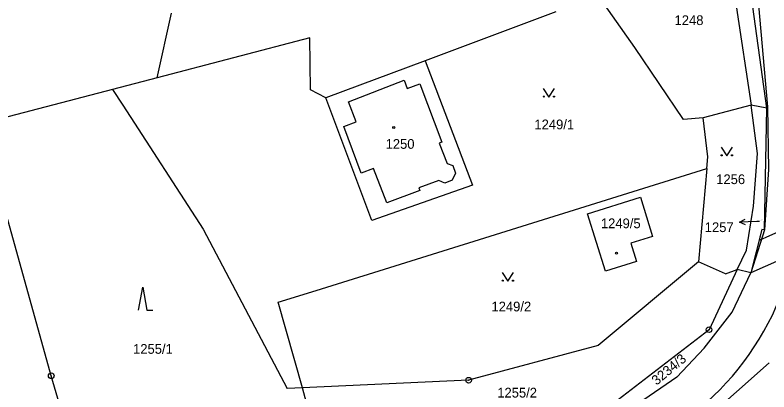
# Model space of a CAD drawing. Extents: x -736345 to -729997, y -1130177 to -1122501.
# Drawn here: x -734075.9 to -733944, y -1126906.1 to -1126840.2 of the extents above; entities that cross this region are included whole.
import ezdxf

# ---------------------------------------------------------------- set-up
doc = ezdxf.new("R2010")
doc.units = 0
for name, color, linetype in [('Vrstva 1', 7, 'Continuous'), ('Vrstva 16', 7, 'Continuous'), ('Vrstva 18', 7, 'Continuous'), ('Vrstva 19', 7, 'Continuous'), ('Vrstva 25', 7, 'Continuous'), ('Vrstva 4', 7, 'Continuous')]:
    doc.layers.add(name, color=color, linetype=linetype)

msp = doc.modelspace()

# ---------------------------------------------------------------- linework, layer by layer
at = {"layer": 'Vrstva 1'}
for points in [[(-733952.31, -1126821.15), (-733947.1, -1126855.94)], [(-733967.46, -1126845.87), (-733975.24, -1126834.74)], [(-733944.32, -1126856.48), (-733947.34, -1126834.89)], [(-733945.98, -1126836.41), (-733944.21, -1126856.25)], [(-734051.04, -1126851.13), (-734048.52, -1126839.86)], [(-733981.26, -1126839.64), (-734004.15, -1126848.16)], [(-734024.3, -1126844.16), (-734051.04, -1126851.13)], [(-734024.21, -1126853.27), (-734024.3, -1126844.16)], [(-733958.93, -1126858.46), (-733967.46, -1126845.87)], [(-734004.15, -1126848.16), (-734021.53, -1126854.63)], [(-734004.15, -1126848.16), (-733995.85, -1126869.92)], [(-734051.04, -1126851.13), (-734058.86, -1126853.17)], [(-734058.86, -1126853.17), (-734079.66, -1126858.6)], [(-734058.86, -1126853.17), (-734057.08, -1126855.91)], [(-734021.53, -1126854.63), (-734024.21, -1126853.27)], [(-734013.46, -1126876.12), (-734021.53, -1126854.63)], [(-734057.08, -1126855.91), (-734042.99, -1126877.6)], [(-733947.1, -1126855.94), (-733955.48, -1126858.17)], [(-733945.95, -1126864.4), (-733947.1, -1126855.94)], [(-733944.32, -1126856.48), (-733947.1, -1126855.94)], [(-733944.76, -1126877.73), (-733944.32, -1126856.48)], [(-733944.21, -1126856.25), (-733944.02, -1126867.2)], [(-733955.48, -1126858.17), (-733958.93, -1126858.46)], [(-733954.64, -1126864.97), (-733955.48, -1126858.17)], [(-733946.67, -1126873.57), (-733945.95, -1126864.4)], [(-734069.58, -1126903.24), (-734080.34, -1126864.84)], [(-733954.82, -1126866.98), (-733954.64, -1126864.97)], [(-734023.23, -1126888.3), (-733954.82, -1126866.98)], [(-733954.82, -1126866.98), (-733956.29, -1126883.31)], [(-733944.02, -1126867.2), (-733944.76, -1126877.73)], [(-733995.85, -1126869.92), (-734013.46, -1126876.12)], [(-733975.72, -1126874.9), (-733966.46, -1126872)], [(-733966.46, -1126872), (-733964.36, -1126878.88)], [(-733947.92, -1126881.25), (-733946.67, -1126873.57)], [(-733972.6, -1126884.94), (-733975.72, -1126874.9)], [(-734042.99, -1126877.6), (-734028.32, -1126905.45)], [(-733945.23, -1126877.65), (-733947.14, -1126885.22)], [(-733944.76, -1126877.73), (-733947.14, -1126885.22)], [(-733944.76, -1126877.73), (-733945.23, -1126877.65)], [(-733964.36, -1126878.88), (-733968.16, -1126880.04)], [(-733968.16, -1126880.04), (-733967.17, -1126883.26)], [(-733949.51, -1126884.63), (-733947.92, -1126881.25)], [(-733939.6, -1126881.9), (-733947.14, -1126885.22)], [(-733956.29, -1126883.31), (-733973.87, -1126897.96)], [(-733967.17, -1126883.26), (-733972.6, -1126884.94)], [(-733951.56, -1126885.39), (-733956.29, -1126883.31)], [(-733949.51, -1126884.63), (-733954.46, -1126895.18)], [(-733951.56, -1126885.39), (-733949.51, -1126884.63)], [(-733950.43, -1126892.09), (-733947.14, -1126885.22)], [(-733947.14, -1126885.22), (-733949.51, -1126884.63)], [(-734029.84, -1126890.36), (-734023.23, -1126888.3)], [(-734025.63, -1126905.32), (-734029.84, -1126890.36)], [(-733955.33, -1126898.42), (-733950.43, -1126892.09)], [(-733954.46, -1126895.18), (-733970.34, -1126907.47)], [(-733973.87, -1126897.96), (-733996.53, -1126904.02)], [(-733960.11, -1126903.49), (-733955.33, -1126898.42)], [(-733955.35, -1126911.11), (-733943.93, -1126901)], [(-734061.05, -1126932.21), (-734069.58, -1126903.24)], [(-733996.53, -1126904.02), (-734025.63, -1126905.32)], [(-733960.11, -1126903.49), (-733966.81, -1126908.06)], [(-734025.63, -1126905.32), (-734028.32, -1126905.45)], [(-734020.94, -1126922.82), (-734025.63, -1126905.32)]]:
    msp.add_lwpolyline(points, dxfattribs=at)
at = {"layer": 'Vrstva 16'}
for points in [[(-733945.64, -1126876.24), (-733946.1, -1126876.26)], [(-733945.5, -1126879.5), (-733944.46, -1126879.03)]]:
    msp.add_lwpolyline(points, dxfattribs=at)
at = {"layer": 'Vrstva 25'}
for points in [[(-733983.48, -1126853.03), (-733982.48, -1126854.53), (-733981.48, -1126853.03)], [(-733952.34, -1126863.3), (-733951.34, -1126864.8), (-733950.34, -1126863.3)], [(-733948.072, -1126876.86), (-733949.096, -1126876.411), (-733948.122, -1126875.862)], [(-733946.1, -1126876.26), (-733949.096, -1126876.411)], [(-733944.46, -1126879.03), (-733941.726, -1126877.796)], [(-733990.66, -1126885.2), (-733989.66, -1126886.7), (-733988.66, -1126885.2)], [(-734054.33, -1126891.75), (-734053.58, -1126887.75), (-734052.83, -1126891.75), (-734051.83, -1126891.75)]]:
    msp.add_lwpolyline(points, dxfattribs=at)
for centre, radius in [((-733983.38, -1126854.43), 0.1), ((-733981.58, -1126854.43), 0.1), ((-734009.65, -1126859.83), 0.175), ((-733952.24, -1126864.7), 0.1), ((-733950.44, -1126864.7), 0.1), ((-733970.67, -1126881.82), 0.175), ((-733990.56, -1126886.6), 0.1), ((-733988.76, -1126886.6), 0.1), ((-733954.46, -1126895.18), 0.5), ((-733954.46, -1126895.18), 0.032), ((-734069.58, -1126903.24), 0.5), ((-734069.58, -1126903.24), 0.032), ((-733996.53, -1126904.02), 0.5), ((-733996.53, -1126904.02), 0.032)]:
    msp.add_circle(centre, radius, dxfattribs=at)
at = {"layer": 'Vrstva 4'}
for points in [[(-734017.56, -1126855.35), (-734007.82, -1126851.59)], [(-734007.82, -1126851.59), (-734007.27, -1126853.04)], [(-734007.27, -1126853.04), (-734005.1, -1126852.2)], [(-734005.1, -1126852.2), (-734001.23, -1126862.39)], [(-734016.23, -1126858.87), (-734017.56, -1126855.35)], [(-734018.39, -1126859.69), (-734016.23, -1126858.87)], [(-734015.33, -1126867.8), (-734018.39, -1126859.69)], [(-734001.23, -1126862.39), (-734001.7, -1126862.57)], [(-734001.7, -1126862.57), (-734000.31, -1126866.12)], [(-734013.17, -1126866.99), (-734015.33, -1126867.8)], [(-734010.86, -1126873.01), (-734013.17, -1126866.99)], [(-734000.31, -1126866.12), (-733999.31, -1126866.47)], [(-733999.31, -1126866.47), (-733998.81, -1126867.79)], [(-733998.81, -1126867.79), (-733999.39, -1126869.07)], [(-734001.75, -1126869.08), (-734005.23, -1126870.36)], [(-734000.69, -1126869.56), (-734001.75, -1126869.08)], [(-733999.39, -1126869.07), (-734000.69, -1126869.56)], [(-734005.06, -1126870.83), (-734010.86, -1126873.01)], [(-734005.23, -1126870.36), (-734005.06, -1126870.83)]]:
    msp.add_lwpolyline(points, dxfattribs=at)
msp.add_arc((-733988.456, -1126870.692), 50.125, 288.14314, 347.08217, dxfattribs=at)

# ---------------------------------------------------------------- texts
at = {"layer": 'Vrstva 16'}
msp.add_text('1257', height=1.7, dxfattribs=at).set_placement((-733955.206, -1126878.12))
at = {"layer": 'Vrstva 18'}
for s, height, p in [('1248', 1.7, (-733960.49, -1126841.93)), ('1249/1', 1.7, (-733985.02, -1126860.15)), ('1256', 1.7, (-733953.2, -1126869.73)), ('1257', 0.1, (-733945.44, -1126876.04)), ('1249/2', 1.7, (-733992.54, -1126891.98)), ('1255/1', 1.7, (-734055.26, -1126899.39)), ('1255/2', 1.7, (-733991.52, -1126907.04))]:
    msp.add_text(s, height=height, dxfattribs=at).set_placement(p)
for s, height, rotation, p in [('3241/3', 0.1, 75.2006, (-733945.642, -1126879.256)), ('3234/3', 1.7, 39.60031, (-733963.634, -1126904.979))]:
    msp.add_text(s, height=height, rotation=rotation, dxfattribs=at).set_placement(p)
at = {"layer": 'Vrstva 19'}
for s, p in [('1250', (-734011.06, -1126863.56)), ('1249/5', (-733973.38, -1126877.44))]:
    msp.add_text(s, height=1.7, dxfattribs=at).set_placement(p)

doc.saveas('drawing.dxf')
